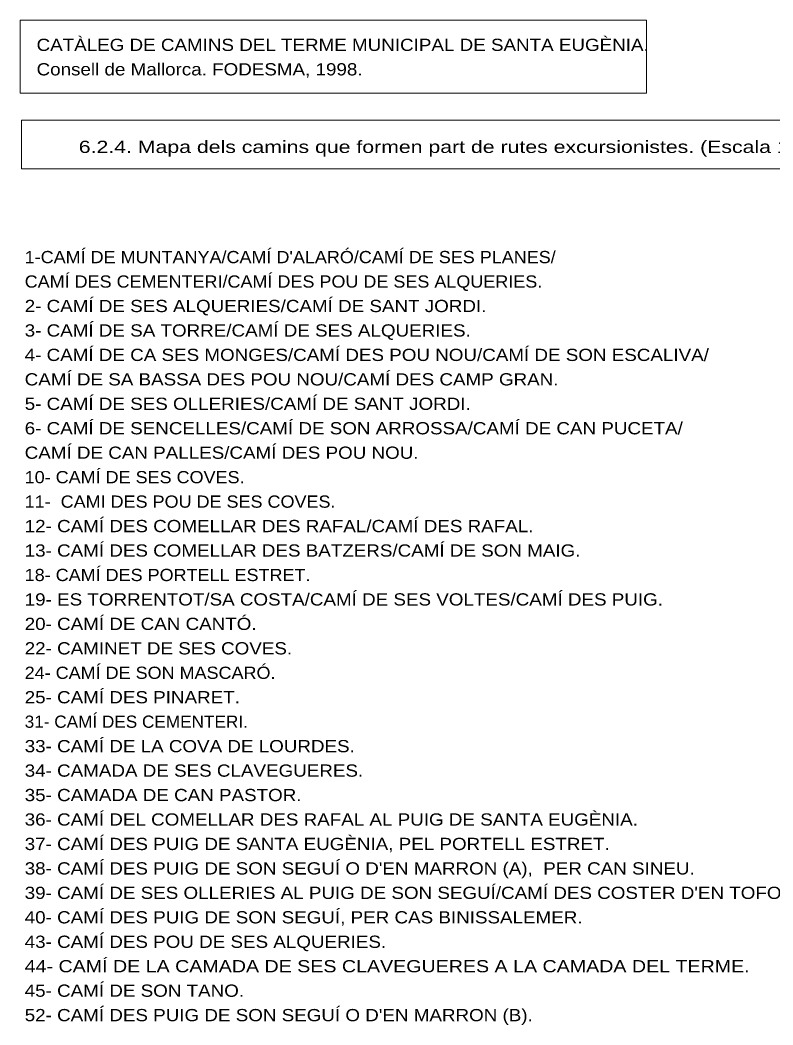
# Model space of a CAD drawing. Extents: x 476989 to 498418, y 4381813 to 4416555.
# Drawn here: x 480312 to 483391, y 4384808 to 4388918 of the extents above; entities that cross this region are included whole.
import ezdxf
from ezdxf.enums import TextEntityAlignment as Align

# ---------------------------------------------------------------- set-up
doc = ezdxf.new("R2010")
doc.units = 0
doc.header["$LTSCALE"] = 20
doc.layers.add('13', color=7, linetype='Continuous', lineweight=13)

msp = doc.modelspace()

# ---------------------------------------------------------------- linework, layer by layer
at = {"layer": '13'}
for points in [[(480311.63, 4388917.52), (482873.59, 4388917.52), (482873.59, 4388618.76), (480311.63, 4388618.76)], [(480316.85, 4388508.69), (484033.85, 4388508.69), (484033.85, 4388309.52), (480316.85, 4388309.52)]]:
    msp.add_lwpolyline(points, close=True, dxfattribs=at)

# ---------------------------------------------------------------- texts
for s, width, p in [('CATÀLEG DE CAMINS DEL TERME MUNICIPAL DE SANTA EUGÈNIA.', 1.15, (480379.02, 4388791.28)), ('Consell de Mallorca. FODESMA, 1998.', 1.15, (480379.02, 4388691.28)), ("1-CAMÍ DE MUNTANYA/CAMÍ D'ALARÓ/CAMÍ DE SES PLANES/", 1.1, (480330.43, 4387923.38)), ('CAMÍ DES CEMENTERI/CAMÍ DES POU DE SES ALQUERIES.', 1.1, (480330.43, 4387823.38)), ('2- CAMÍ DE SES ALQUERIES/CAMÍ DE SANT JORDI.', 1.15, (480330.43, 4387723.38)), ('3- CAMÍ DE SA TORRE/CAMÍ DE SES ALQUERIES.', 1.15, (480330.43, 4387623.38)), ('4- CAMÍ DE CA SES MONGES/CAMÍ DES POU NOU/CAMÍ DE SON ESCALIVA/', 1.15, (480330.43, 4387523.38)), ('CAMÍ DE SA BASSA DES POU NOU/CAMÍ DES CAMP GRAN.', 1.15, (480330.43, 4387423.38)), ('5- CAMÍ DE SES OLLERIES/CAMÍ DE SANT JORDI.', 1.15, (480330.43, 4387323.38)), ('6- CAMÍ DE SENCELLES/CAMÍ DE SON ARROSSA/CAMÍ DE CAN PUCETA/', 1.15, (480330.43, 4387223.38)), ('CAMÍ DE CAN PALLES/CAMÍ DES POU NOU.', 1.15, (480330.43, 4387123.38)), ('10- CAMÍ DE SES COVES.', 1.1, (480330.43, 4387023.38)), ('11-  CAMI DES POU DE SES COVES.', 1.1, (480330.43, 4386923.38)), ('12- CAMÍ DES COMELLAR DES RAFAL/CAMÍ DES RAFAL.', 1.15, (480330.43, 4386823.38)), ('13- CAMÍ DES COMELLAR DES BATZERS/CAMÍ DE SON MAIG.', 1.15, (480330.43, 4386723.38)), ('18- CAMÍ DES PORTELL ESTRET.', 1.1, (480330.43, 4386623.38)), ('19- ES TORRENTOT/SA COSTA/CAMÍ DE SES VOLTES/CAMÍ DES PUIG.', 1.15, (480330.43, 4386523.38)), ('20- CAMÍ DE CAN CANTÓ.', 1.15, (480330.43, 4386423.38)), ('22- CAMINET DE SES COVES.', 1.15, (480330.43, 4386323.38)), ('24- CAMÍ DE SON MASCARÓ.', 1.1, (480330.43, 4386223.38)), ('25- CAMÍ DES PINARET.', 1.15, (480330.43, 4386123.38)), ('31- CAMÍ DES CEMENTERI.', 1.05, (480330.43, 4386023.38)), ('33- CAMÍ DE LA COVA DE LOURDES.', 1.15, (480330.43, 4385923.38)), ('34- CAMADA DE SES CLAVEGUERES.', 1.15, (480330.43, 4385823.38)), ('35- CAMADA DE CAN PASTOR.', 1.15, (480330.43, 4385723.38)), ('36- CAMÍ DEL COMELLAR DES RAFAL AL PUIG DE SANTA EUGÈNIA.', 1.15, (480330.43, 4385623.38)), ('37- CAMÍ DES PUIG DE SANTA EUGÈNIA, PEL PORTELL ESTRET.', 1.15, (480330.43, 4385523.38)), ("38- CAMÍ DES PUIG DE SON SEGUÍ O D'EN MARRON (A),  PER CAN SINEU.", 1.15, (480330.43, 4385423.38)), ("39- CAMÍ DE SES OLLERIES AL PUIG DE SON SEGUÍ/CAMÍ DES COSTER D'EN TOFOL.", 1.15, (480330.43, 4385323.38)), ('40- CAMÍ DES PUIG DE SON SEGUÍ, PER CAS BINISSALEMER.', 1.15, (480330.43, 4385223.38)), ('43- CAMÍ DES POU DE SES ALQUERIES.', 1.15, (480330.43, 4385123.38)), ('44- CAMÍ DE LA CAMADA DE SES CLAVEGUERES A LA CAMADA DEL TERME.', 1.2, (480330.43, 4385023.38)), ('45- CAMÍ DE SON TANO.', 1.15, (480330.43, 4384923.38)), ("52- CAMÍ DES PUIG DE SON SEGUÍ O D'EN MARRON (B).", 1.15, (480330.43, 4384823.38))]:
    msp.add_text(s, height=50, dxfattribs=dict(at, width=width)).set_placement(p)
at = {"layer": '13', "width": 1.3}
msp.add_text('6.2.4. Mapa dels camins que formen part de rutes excursionistes. (Escala 1:25.000)', height=50, dxfattribs=at).set_placement((482162.88, 4388374.15), align=Align.CENTER)

doc.saveas('drawing.dxf')
